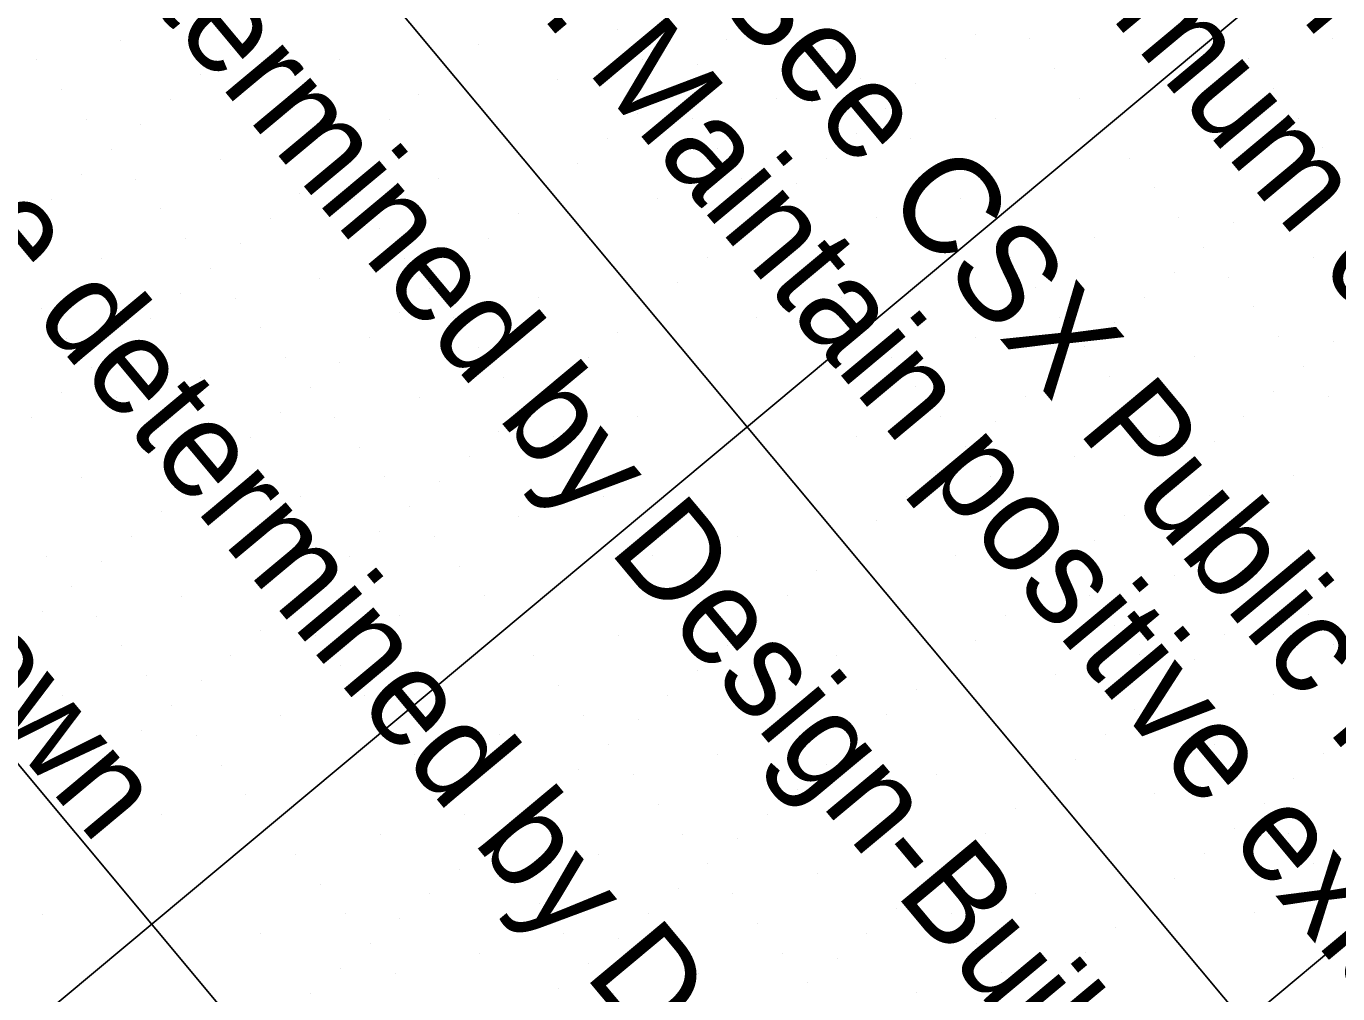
# Model space of a CAD drawing. Extents: x 2042995 to 2043795, y 305365 to 306249.
# Drawn here: x 2043491.39 to 2043525.2, y 305609.11 to 305634.05 of the extents above; entities that cross this region are included whole.
import ezdxf

# ---------------------------------------------------------------- set-up
doc = ezdxf.new("R2010")
doc.units = 0
for name, color, linetype in [('BR_AUTO DIMENSION', 7, 'Continuous'), ('BR_CONCRETE', 7, 'Continuous'), ('BR_GRID DOTS', 7, 'Continuous'), ('BR_GRID LINES', 7, 'Continuous')]:
    doc.layers.add(name, color=color, linetype=linetype)

msp = doc.modelspace()

# ---------------------------------------------------------------- linework, layer by layer
at = {"layer": 'BR_CONCRETE'}
msp.add_spline([(2043139.109, 306017.548), (2043148.199, 306007.16), (2043160.233, 305993.368), (2043172.245, 305979.557), (2043184.234, 305965.727), (2043196.201, 305951.879), (2043208.145, 305938.012), (2043220.067, 305924.126), (2043231.966, 305910.221), (2043243.843, 305896.297), (2043255.698, 305882.355), (2043267.529, 305868.394), (2043279.339, 305854.414), (2043291.126, 305840.415), (2043302.89, 305826.398), (2043314.632, 305812.361), (2043326.352, 305798.306), (2043338.049, 305784.233), (2043349.724, 305770.14), (2043361.376, 305756.029), (2043373.005, 305741.899), (2043384.613, 305727.75), (2043396.197, 305713.582), (2043407.76, 305699.396), (2043419.299, 305685.191), (2043430.817, 305670.967), (2043442.311, 305656.724), (2043453.784, 305642.463), (2043465.234, 305628.182), (2043476.661, 305613.883), (2043488.066, 305599.566), (2043499.448, 305585.229), (2043510.808, 305570.874), (2043522.146, 305556.5), (2043533.461, 305542.107), (2043544.753, 305527.695), (2043547.219, 305524.543)], degree=3, dxfattribs=at)
at = {"layer": 'BR_GRID DOTS'}
for p, q in [((2043493.832, 305633.697), (2043493.832, 305633.697)), ((2043506.636, 305633.967), (2043506.636, 305633.967)), ((2043509.453, 305633.714), (2043509.453, 305633.714)), ((2043515.855, 305633.849), (2043515.855, 305633.849)), ((2043517.263, 305633.723), (2043517.263, 305633.723)), ((2043525.073, 305633.731), (2043525.073, 305633.731)), ((2043496.65, 305633.444), (2043496.65, 305633.444)), ((2043503.051, 305633.579), (2043503.051, 305633.579)), ((2043512.27, 305633.461), (2043512.27, 305633.461)), ((2043491.656, 305633.183), (2043491.656, 305633.183)), ((2043499.467, 305633.191), (2043499.467, 305633.191)), ((2043507.277, 305633.2), (2043507.277, 305633.2)), ((2043508.685, 305633.073), (2043508.685, 305633.073)), ((2043515.087, 305633.208), (2043515.087, 305633.208)), ((2043522.897, 305633.217), (2043522.897, 305633.217)), ((2043495.882, 305632.803), (2043495.882, 305632.803)), ((2043497.291, 305632.677), (2043497.291, 305632.677)), ((2043502.284, 305632.938), (2043502.284, 305632.938)), ((2043505.101, 305632.685), (2043505.101, 305632.685)), ((2043512.911, 305632.694), (2043512.911, 305632.694)), ((2043517.904, 305632.955), (2043517.904, 305632.955)), ((2043492.297, 305632.415), (2043492.297, 305632.415)), ((2043507.918, 305632.432), (2043507.918, 305632.432)), ((2043514.32, 305632.567), (2043514.32, 305632.567)), ((2043523.538, 305632.449), (2043523.538, 305632.449)), ((2043495.115, 305632.162), (2043495.115, 305632.162)), ((2043501.516, 305632.297), (2043501.516, 305632.297)), ((2043510.735, 305632.179), (2043510.735, 305632.179)), ((2043518.545, 305632.188), (2043518.545, 305632.188)), ((2043492.938, 305631.648), (2043492.938, 305631.648)), ((2043497.932, 305631.909), (2043497.932, 305631.909)), ((2043500.749, 305631.656), (2043500.749, 305631.656)), ((2043507.15, 305631.791), (2043507.15, 305631.791)), ((2043508.559, 305631.665), (2043508.559, 305631.665)), ((2043513.552, 305631.926), (2043513.552, 305631.926)), ((2043516.369, 305631.673), (2043516.369, 305631.673)), ((2043524.179, 305631.682), (2043524.179, 305631.682)), ((2043494.347, 305631.521), (2043494.347, 305631.521)), ((2043498.573, 305631.142), (2043498.573, 305631.142)), ((2043499.981, 305631.015), (2043499.981, 305631.015)), ((2043506.383, 305631.15), (2043506.383, 305631.15)), ((2043512.785, 305631.285), (2043512.785, 305631.285)), ((2043514.193, 305631.159), (2043514.193, 305631.159)), ((2043522.003, 305631.167), (2043522.003, 305631.167)), ((2043493.579, 305630.88), (2043493.579, 305630.88)), ((2043509.2, 305630.897), (2043509.2, 305630.897)), ((2043512.017, 305630.644), (2043512.017, 305630.644)), ((2043519.827, 305630.653), (2043519.827, 305630.653)), ((2043524.82, 305630.914), (2043524.82, 305630.914)), ((2043496.397, 305630.627), (2043496.397, 305630.627)), ((2043499.214, 305630.374), (2043499.214, 305630.374)), ((2043505.615, 305630.509), (2043505.615, 305630.509)), ((2043514.834, 305630.391), (2043514.834, 305630.391)), ((2043492.812, 305630.239), (2043492.812, 305630.239)), ((2043494.22, 305630.113), (2043494.22, 305630.113)), ((2043502.031, 305630.121), (2043502.031, 305630.121)), ((2043509.841, 305630.13), (2043509.841, 305630.13)), ((2043511.25, 305630.003), (2043511.25, 305630.003)), ((2043524.053, 305630.273), (2043524.053, 305630.273)), ((2043498.446, 305629.733), (2043498.446, 305629.733)), ((2043504.848, 305629.868), (2043504.848, 305629.868)), ((2043515.475, 305629.624), (2043515.475, 305629.624)), ((2043520.468, 305629.885), (2043520.468, 305629.885)), ((2043523.285, 305629.632), (2043523.285, 305629.632)), ((2043492.044, 305629.598), (2043492.044, 305629.598)), ((2043494.862, 305629.345), (2043494.862, 305629.345)), ((2043499.855, 305629.607), (2043499.855, 305629.607)), ((2043507.665, 305629.615), (2043507.665, 305629.615)), ((2043510.482, 305629.362), (2043510.482, 305629.362)), ((2043497.679, 305629.092), (2043497.679, 305629.092)), ((2043504.08, 305629.227), (2043504.08, 305629.227)), ((2043513.299, 305629.109), (2043513.299, 305629.109)), ((2043521.109, 305629.118), (2043521.109, 305629.118)), ((2043522.518, 305628.991), (2043522.518, 305628.991)), ((2043500.496, 305628.839), (2043500.496, 305628.839)), ((2043509.714, 305628.721), (2043509.714, 305628.721)), ((2043495.503, 305628.578), (2043495.503, 305628.578)), ((2043496.911, 305628.451), (2043496.911, 305628.451)), ((2043503.313, 305628.586), (2043503.313, 305628.586)), ((2043511.123, 305628.595), (2043511.123, 305628.595)), ((2043518.933, 305628.603), (2043518.933, 305628.603)), ((2043521.75, 305628.35), (2043521.75, 305628.35)), ((2043493.326, 305628.063), (2043493.326, 305628.063)), ((2043501.137, 305628.072), (2043501.137, 305628.072)), ((2043502.545, 305627.945), (2043502.545, 305627.945)), ((2043508.947, 305628.08), (2043508.947, 305628.08)), ((2043516.757, 305628.089), (2043516.757, 305628.089)), ((2043524.567, 305628.097), (2043524.567, 305628.097)), ((2043496.144, 305627.81), (2043496.144, 305627.81)), ((2043511.764, 305627.827), (2043511.764, 305627.827)), ((2043520.983, 305627.709), (2043520.983, 305627.709)), ((2043498.961, 305627.557), (2043498.961, 305627.557)), ((2043501.778, 305627.304), (2043501.778, 305627.304)), ((2043508.179, 305627.439), (2043508.179, 305627.439)), ((2043517.398, 305627.321), (2043517.398, 305627.321)), ((2043522.391, 305627.583), (2043522.391, 305627.583)), ((2043495.376, 305627.169), (2043495.376, 305627.169)), ((2043496.785, 305627.043), (2043496.785, 305627.043)), ((2043504.595, 305627.051), (2043504.595, 305627.051)), ((2043512.405, 305627.06), (2043512.405, 305627.06)), ((2043520.215, 305627.068), (2043520.215, 305627.068)), ((2043491.791, 305626.781), (2043491.791, 305626.781)), ((2043501.01, 305626.663), (2043501.01, 305626.663)), ((2043507.412, 305626.798), (2043507.412, 305626.798)), ((2043523.032, 305626.815), (2043523.032, 305626.815)), ((2043494.609, 305626.528), (2043494.609, 305626.528)), ((2043497.426, 305626.275), (2043497.426, 305626.275)), ((2043502.419, 305626.537), (2043502.419, 305626.537)), ((2043510.229, 305626.545), (2043510.229, 305626.545)), ((2043518.039, 305626.554), (2043518.039, 305626.554)), ((2043519.448, 305626.427), (2043519.448, 305626.427)), ((2043492.432, 305626.013), (2043492.432, 305626.013)), ((2043500.243, 305626.022), (2043500.243, 305626.022)), ((2043506.644, 305626.157), (2043506.644, 305626.157)), ((2043515.863, 305626.039), (2043515.863, 305626.039)), ((2043523.673, 305626.048), (2043523.673, 305626.048)), ((2043525.082, 305625.921), (2043525.082, 305625.921)), ((2043493.841, 305625.887), (2043493.841, 305625.887)), ((2043503.06, 305625.769), (2043503.06, 305625.769)), ((2043518.68, 305625.786), (2043518.68, 305625.786)), ((2043493.073, 305625.246), (2043493.073, 305625.246)), ((2043498.067, 305625.507), (2043498.067, 305625.507)), ((2043499.475, 305625.381), (2043499.475, 305625.381)), ((2043505.877, 305625.516), (2043505.877, 305625.516)), ((2043513.687, 305625.525), (2043513.687, 305625.525)), ((2043521.497, 305625.533), (2043521.497, 305625.533)), ((2043524.314, 305625.28), (2043524.314, 305625.28)), ((2043495.891, 305624.993), (2043495.891, 305624.993)), ((2043503.701, 305625.002), (2043503.701, 305625.002)), ((2043517.913, 305625.145), (2043517.913, 305625.145)), ((2043519.321, 305625.019), (2043519.321, 305625.019)), ((2043492.306, 305624.605), (2043492.306, 305624.605)), ((2043498.708, 305624.74), (2043498.708, 305624.74)), ((2043505.109, 305624.875), (2043505.109, 305624.875)), ((2043514.328, 305624.757), (2043514.328, 305624.757)), ((2043523.547, 305624.639), (2043523.547, 305624.639)), ((2043493.715, 305624.478), (2043493.715, 305624.478)), ((2043501.525, 305624.487), (2043501.525, 305624.487)), ((2043504.342, 305624.234), (2043504.342, 305624.234)), ((2043517.145, 305624.504), (2043517.145, 305624.504)), ((2043519.962, 305624.251), (2043519.962, 305624.251)), ((2043524.955, 305624.513), (2043524.955, 305624.513)), ((2043491.538, 305623.964), (2043491.538, 305623.964)), ((2043497.94, 305624.099), (2043497.94, 305624.099)), ((2043499.349, 305623.972), (2043499.349, 305623.972)), ((2043507.159, 305623.981), (2043507.159, 305623.981)), ((2043514.969, 305623.99), (2043514.969, 305623.99)), ((2043522.779, 305623.998), (2043522.779, 305623.998)), ((2043494.356, 305623.711), (2043494.356, 305623.711)), ((2043503.574, 305623.593), (2043503.574, 305623.593)), ((2043516.378, 305623.863), (2043516.378, 305623.863)), ((2043497.173, 305623.458), (2043497.173, 305623.458)), ((2043499.99, 305623.205), (2043499.99, 305623.205)), ((2043504.983, 305623.466), (2043504.983, 305623.466)), ((2043512.793, 305623.475), (2043512.793, 305623.475)), ((2043515.61, 305623.222), (2043515.61, 305623.222)), ((2043520.603, 305623.484), (2043520.603, 305623.484)), ((2043522.012, 305623.357), (2043522.012, 305623.357)), ((2043494.997, 305622.943), (2043494.997, 305622.943)), ((2043502.807, 305622.952), (2043502.807, 305622.952)), ((2043518.427, 305622.969), (2043518.427, 305622.969)), ((2043496.405, 305622.817), (2043496.405, 305622.817)), ((2043505.624, 305622.699), (2043505.624, 305622.699)), ((2043514.843, 305622.581), (2043514.843, 305622.581)), ((2043521.244, 305622.716), (2043521.244, 305622.716)), ((2043492.821, 305622.429), (2043492.821, 305622.429)), ((2043500.631, 305622.437), (2043500.631, 305622.437)), ((2043502.039, 305622.311), (2043502.039, 305622.311)), ((2043516.251, 305622.455), (2043516.251, 305622.455)), ((2043524.061, 305622.463), (2043524.061, 305622.463)), ((2043495.638, 305622.176), (2043495.638, 305622.176)), ((2043498.455, 305621.923), (2043498.455, 305621.923)), ((2043506.265, 305621.931), (2043506.265, 305621.931)), ((2043514.075, 305621.94), (2043514.075, 305621.94)), ((2043520.477, 305622.075), (2043520.477, 305622.075)), ((2043521.885, 305621.949), (2043521.885, 305621.949)), ((2043494.87, 305621.535), (2043494.87, 305621.535)), ((2043501.272, 305621.67), (2043501.272, 305621.67)), ((2043516.892, 305621.687), (2043516.892, 305621.687)), ((2043496.279, 305621.408), (2043496.279, 305621.408)), ((2043504.089, 305621.417), (2043504.089, 305621.417)), ((2043513.308, 305621.299), (2043513.308, 305621.299)), ((2043519.709, 305621.434), (2043519.709, 305621.434)), ((2043522.526, 305621.181), (2043522.526, 305621.181)), ((2043494.103, 305620.894), (2043494.103, 305620.894)), ((2043500.504, 305621.029), (2043500.504, 305621.029)), ((2043501.913, 305620.902), (2043501.913, 305620.902)), ((2043509.723, 305620.911), (2043509.723, 305620.911)), ((2043517.533, 305620.919), (2043517.533, 305620.919)), ((2043496.92, 305620.641), (2043496.92, 305620.641)), ((2043512.54, 305620.658), (2043512.54, 305620.658)), ((2043518.942, 305620.793), (2043518.942, 305620.793)), ((2043491.927, 305620.379), (2043491.927, 305620.379)), ((2043493.335, 305620.253), (2043493.335, 305620.253)), ((2043499.737, 305620.388), (2043499.737, 305620.388)), ((2043507.547, 305620.396), (2043507.547, 305620.396)), ((2043515.357, 305620.405), (2043515.357, 305620.405)), ((2043518.174, 305620.152), (2043518.174, 305620.152)), ((2043523.167, 305620.414), (2043523.167, 305620.414)), ((2043524.576, 305620.287), (2043524.576, 305620.287)), ((2043497.561, 305619.873), (2043497.561, 305619.873)), ((2043502.554, 305620.135), (2043502.554, 305620.135)), ((2043511.773, 305620.017), (2043511.773, 305620.017)), ((2043520.991, 305619.899), (2043520.991, 305619.899)), ((2043492.568, 305619.612), (2043492.568, 305619.612)), ((2043498.969, 305619.747), (2043498.969, 305619.747)), ((2043508.188, 305619.629), (2043508.188, 305619.629)), ((2043517.407, 305619.511), (2043517.407, 305619.511)), ((2043523.808, 305619.646), (2043523.808, 305619.646)), ((2043495.385, 305619.359), (2043495.385, 305619.359)), ((2043503.195, 305619.367), (2043503.195, 305619.367)), ((2043511.005, 305619.376), (2043511.005, 305619.376)), ((2043518.815, 305619.384), (2043518.815, 305619.384)), ((2043491.8, 305618.971), (2043491.8, 305618.971)), ((2043493.209, 305618.844), (2043493.209, 305618.844)), ((2043498.202, 305619.106), (2043498.202, 305619.106)), ((2043501.019, 305618.853), (2043501.019, 305618.853)), ((2043508.829, 305618.861), (2043508.829, 305618.861)), ((2043516.639, 305618.87), (2043516.639, 305618.87)), ((2043523.041, 305619.005), (2043523.041, 305619.005)), ((2043524.45, 305618.878), (2043524.45, 305618.878)), ((2043497.434, 305618.465), (2043497.434, 305618.465)), ((2043510.238, 305618.735), (2043510.238, 305618.735)), ((2043519.456, 305618.617), (2043519.456, 305618.617)), ((2043498.843, 305618.338), (2043498.843, 305618.338)), ((2043506.653, 305618.347), (2043506.653, 305618.347)), ((2043515.872, 305618.229), (2043515.872, 305618.229)), ((2043522.273, 305618.364), (2043522.273, 305618.364)), ((2043493.85, 305618.077), (2043493.85, 305618.077)), ((2043496.667, 305617.824), (2043496.667, 305617.824)), ((2043504.477, 305617.832), (2043504.477, 305617.832)), ((2043509.47, 305618.094), (2043509.47, 305618.094)), ((2043512.287, 305617.841), (2043512.287, 305617.841)), ((2043520.097, 305617.849), (2043520.097, 305617.849)), ((2043525.091, 305618.111), (2043525.091, 305618.111)), ((2043499.484, 305617.571), (2043499.484, 305617.571)), ((2043508.703, 305617.453), (2043508.703, 305617.453)), ((2043515.104, 305617.588), (2043515.104, 305617.588)), ((2043521.506, 305617.723), (2043521.506, 305617.723)), ((2043494.491, 305617.309), (2043494.491, 305617.309)), ((2043495.899, 305617.183), (2043495.899, 305617.183)), ((2043510.111, 305617.326), (2043510.111, 305617.326)), ((2043517.921, 305617.335), (2043517.921, 305617.335)), ((2043492.315, 305616.795), (2043492.315, 305616.795)), ((2043500.125, 305616.803), (2043500.125, 305616.803)), ((2043505.118, 305617.065), (2043505.118, 305617.065)), ((2043507.935, 305616.812), (2043507.935, 305616.812)), ((2043514.337, 305616.947), (2043514.337, 305616.947)), ((2043520.738, 305617.082), (2043520.738, 305617.082)), ((2043523.556, 305616.829), (2043523.556, 305616.829)), ((2043495.132, 305616.542), (2043495.132, 305616.542)), ((2043510.752, 305616.559), (2043510.752, 305616.559)), ((2043519.971, 305616.441), (2043519.971, 305616.441)), ((2043497.949, 305616.289), (2043497.949, 305616.289)), ((2043505.759, 305616.297), (2043505.759, 305616.297)), ((2043507.168, 305616.171), (2043507.168, 305616.171)), ((2043513.569, 305616.306), (2043513.569, 305616.306)), ((2043521.379, 305616.314), (2043521.379, 305616.314)), ((2043494.364, 305615.901), (2043494.364, 305615.901)), ((2043495.773, 305615.774), (2043495.773, 305615.774)), ((2043503.583, 305615.783), (2043503.583, 305615.783)), ((2043511.393, 305615.791), (2043511.393, 305615.791)), ((2043519.203, 305615.8), (2043519.203, 305615.8)), ((2043506.4, 305615.53), (2043506.4, 305615.53)), ((2043512.802, 305615.665), (2043512.802, 305615.665)), ((2043522.02, 305615.547), (2043522.02, 305615.547)), ((2043493.597, 305615.26), (2043493.597, 305615.26)), ((2043501.407, 305615.268), (2043501.407, 305615.268)), ((2043509.217, 305615.277), (2043509.217, 305615.277)), ((2043518.436, 305615.159), (2043518.436, 305615.159)), ((2043524.838, 305615.294), (2043524.838, 305615.294)), ((2043496.414, 305615.007), (2043496.414, 305615.007)), ((2043505.632, 305614.889), (2043505.632, 305614.889)), ((2043507.041, 305614.762), (2043507.041, 305614.762)), ((2043512.034, 305615.024), (2043512.034, 305615.024)), ((2043514.851, 305614.771), (2043514.851, 305614.771)), ((2043522.661, 305614.779), (2043522.661, 305614.779)), ((2043492.829, 305614.619), (2043492.829, 305614.619)), ((2043502.048, 305614.501), (2043502.048, 305614.501)), ((2043517.668, 305614.518), (2043517.668, 305614.518)), ((2043524.07, 305614.653), (2043524.07, 305614.653)), ((2043497.055, 305614.239), (2043497.055, 305614.239)), ((2043504.865, 305614.248), (2043504.865, 305614.248)), ((2043511.267, 305614.383), (2043511.267, 305614.383)), ((2043512.675, 305614.256), (2043512.675, 305614.256)), ((2043520.485, 305614.265), (2043520.485, 305614.265)), ((2043492.062, 305613.978), (2043492.062, 305613.978)), ((2043502.689, 305613.733), (2043502.689, 305613.733)), ((2043507.682, 305613.995), (2043507.682, 305613.995)), ((2043510.499, 305613.742), (2043510.499, 305613.742)), ((2043516.901, 305613.877), (2043516.901, 305613.877)), ((2043523.303, 305614.012), (2043523.303, 305614.012)), ((2043494.879, 305613.725), (2043494.879, 305613.725)), ((2043504.097, 305613.607), (2043504.097, 305613.607)), ((2043513.316, 305613.489), (2043513.316, 305613.489)), ((2043500.513, 305613.219), (2043500.513, 305613.219)), ((2043508.323, 305613.227), (2043508.323, 305613.227)), ((2043509.732, 305613.101), (2043509.732, 305613.101)), ((2043516.133, 305613.236), (2043516.133, 305613.236)), ((2043522.535, 305613.371), (2043522.535, 305613.371)), ((2043523.944, 305613.244), (2043523.944, 305613.244)), ((2043503.33, 305612.966), (2043503.33, 305612.966)), ((2043513.957, 305612.721), (2043513.957, 305612.721)), ((2043521.767, 305612.73), (2043521.767, 305612.73)), ((2043498.337, 305612.704), (2043498.337, 305612.704)), ((2043506.147, 305612.713), (2043506.147, 305612.713)), ((2043508.964, 305612.46), (2043508.964, 305612.46)), ((2043515.366, 305612.595), (2043515.366, 305612.595)), ((2043524.585, 305612.477), (2043524.585, 305612.477)), ((2043502.562, 305612.325), (2043502.562, 305612.325)), ((2043503.971, 305612.198), (2043503.971, 305612.198)), ((2043511.781, 305612.207), (2043511.781, 305612.207)), ((2043521, 305612.089), (2043521, 305612.089)), ((2043498.978, 305611.937), (2043498.978, 305611.937)), ((2043508.197, 305611.819), (2043508.197, 305611.819)), ((2043514.598, 305611.954), (2043514.598, 305611.954)), ((2043517.415, 305611.701), (2043517.415, 305611.701)), ((2043501.795, 305611.684), (2043501.795, 305611.684)), ((2043504.612, 305611.431), (2043504.612, 305611.431)), ((2043509.605, 305611.692), (2043509.605, 305611.692)), ((2043520.232, 305611.448), (2043520.232, 305611.448)), ((2043491.809, 305611.16), (2043491.809, 305611.16)), ((2043499.619, 305611.169), (2043499.619, 305611.169)), ((2043501.027, 305611.043), (2043501.027, 305611.043)), ((2043507.429, 305611.178), (2043507.429, 305611.178)), ((2043513.831, 305611.313), (2043513.831, 305611.313)), ((2043515.239, 305611.186), (2043515.239, 305611.186)), ((2043523.05, 305611.195), (2043523.05, 305611.195)), ((2043510.246, 305610.925), (2043510.246, 305610.925)), ((2043519.465, 305610.807), (2043519.465, 305610.807)), ((2043497.443, 305610.655), (2043497.443, 305610.655)), ((2043500.26, 305610.402), (2043500.26, 305610.402)), ((2043505.253, 305610.663), (2043505.253, 305610.663)), ((2043506.662, 305610.537), (2043506.662, 305610.537)), ((2043513.063, 305610.672), (2043513.063, 305610.672)), ((2043515.88, 305610.419), (2043515.88, 305610.419)), ((2043503.077, 305610.149), (2043503.077, 305610.149)), ((2043510.887, 305610.157), (2043510.887, 305610.157)), ((2043512.296, 305610.031), (2043512.296, 305610.031)), ((2043518.697, 305610.166), (2043518.697, 305610.166)), ((2043499.492, 305609.761), (2043499.492, 305609.761)), ((2043505.894, 305609.896), (2043505.894, 305609.896)), ((2043500.901, 305609.634), (2043500.901, 305609.634)), ((2043508.711, 305609.643), (2043508.711, 305609.643)), ((2043511.528, 305609.39), (2043511.528, 305609.39)), ((2043516.521, 305609.651), (2043516.521, 305609.651)), ((2043517.93, 305609.525), (2043517.93, 305609.525)), ((2043498.725, 305609.119), (2043498.725, 305609.119)), ((2043505.126, 305609.255), (2043505.126, 305609.255)), ((2043506.535, 305609.128), (2043506.535, 305609.128)), ((2043514.345, 305609.137), (2043514.345, 305609.137))]:
    msp.add_line(p, q, dxfattribs=at)
at = {"layer": 'BR_GRID LINES'}
for p, q in [((2043153.138, 306050.98), (2043584.762, 305534.185)), ((2043137.788, 306038.16), (2043569.411, 305521.364)), ((2043540.677, 305649.369), (2043433.224, 305559.625)), ((2043553.497, 305634.019), (2043446.045, 305544.275))]:
    msp.add_line(p, q, dxfattribs=at)

# ---------------------------------------------------------------- texts
at = {"layer": 'BR_AUTO DIMENSION'}
for s, p in [('Minimum Vertical Clearance required, measured from top of high rail to lowest', (2043497.504, 305683.824)), ('point of superstructure, in the horizontal clearance area that extends 6\'-0"', (2043494.626, 305681.42)), ('on either side of, and perpendicular to, the centerline of outer tracks', (2043491.748, 305679.016)), ('(future track arrangement). Contractor shall verify top of rail elevations', (2043488.87, 305676.613)), ('prior to construction to confirm minimum clearance requirement is met.', (2043485.992, 305674.209)), ('Future ditches are not shown. See CSX Public Projects Manual for ', (2043480.235, 305669.401)), ('minimum future ditch section. Maintain positive existing ditch drainage.', (2043477.357, 305666.997)), ('Finished Grade to be determined by Design-Build Team', (2043471.601, 305662.19)), ('Foundation type/size to be determined by Design-Build Team', (2043465.844, 305657.382)), ('CSX Protective Fencing not shown', (2043460.088, 305652.574))]:
    msp.add_text(s, height=2.5, rotation=309.8684, dxfattribs=at).set_placement(p)

doc.saveas('drawing.dxf')
